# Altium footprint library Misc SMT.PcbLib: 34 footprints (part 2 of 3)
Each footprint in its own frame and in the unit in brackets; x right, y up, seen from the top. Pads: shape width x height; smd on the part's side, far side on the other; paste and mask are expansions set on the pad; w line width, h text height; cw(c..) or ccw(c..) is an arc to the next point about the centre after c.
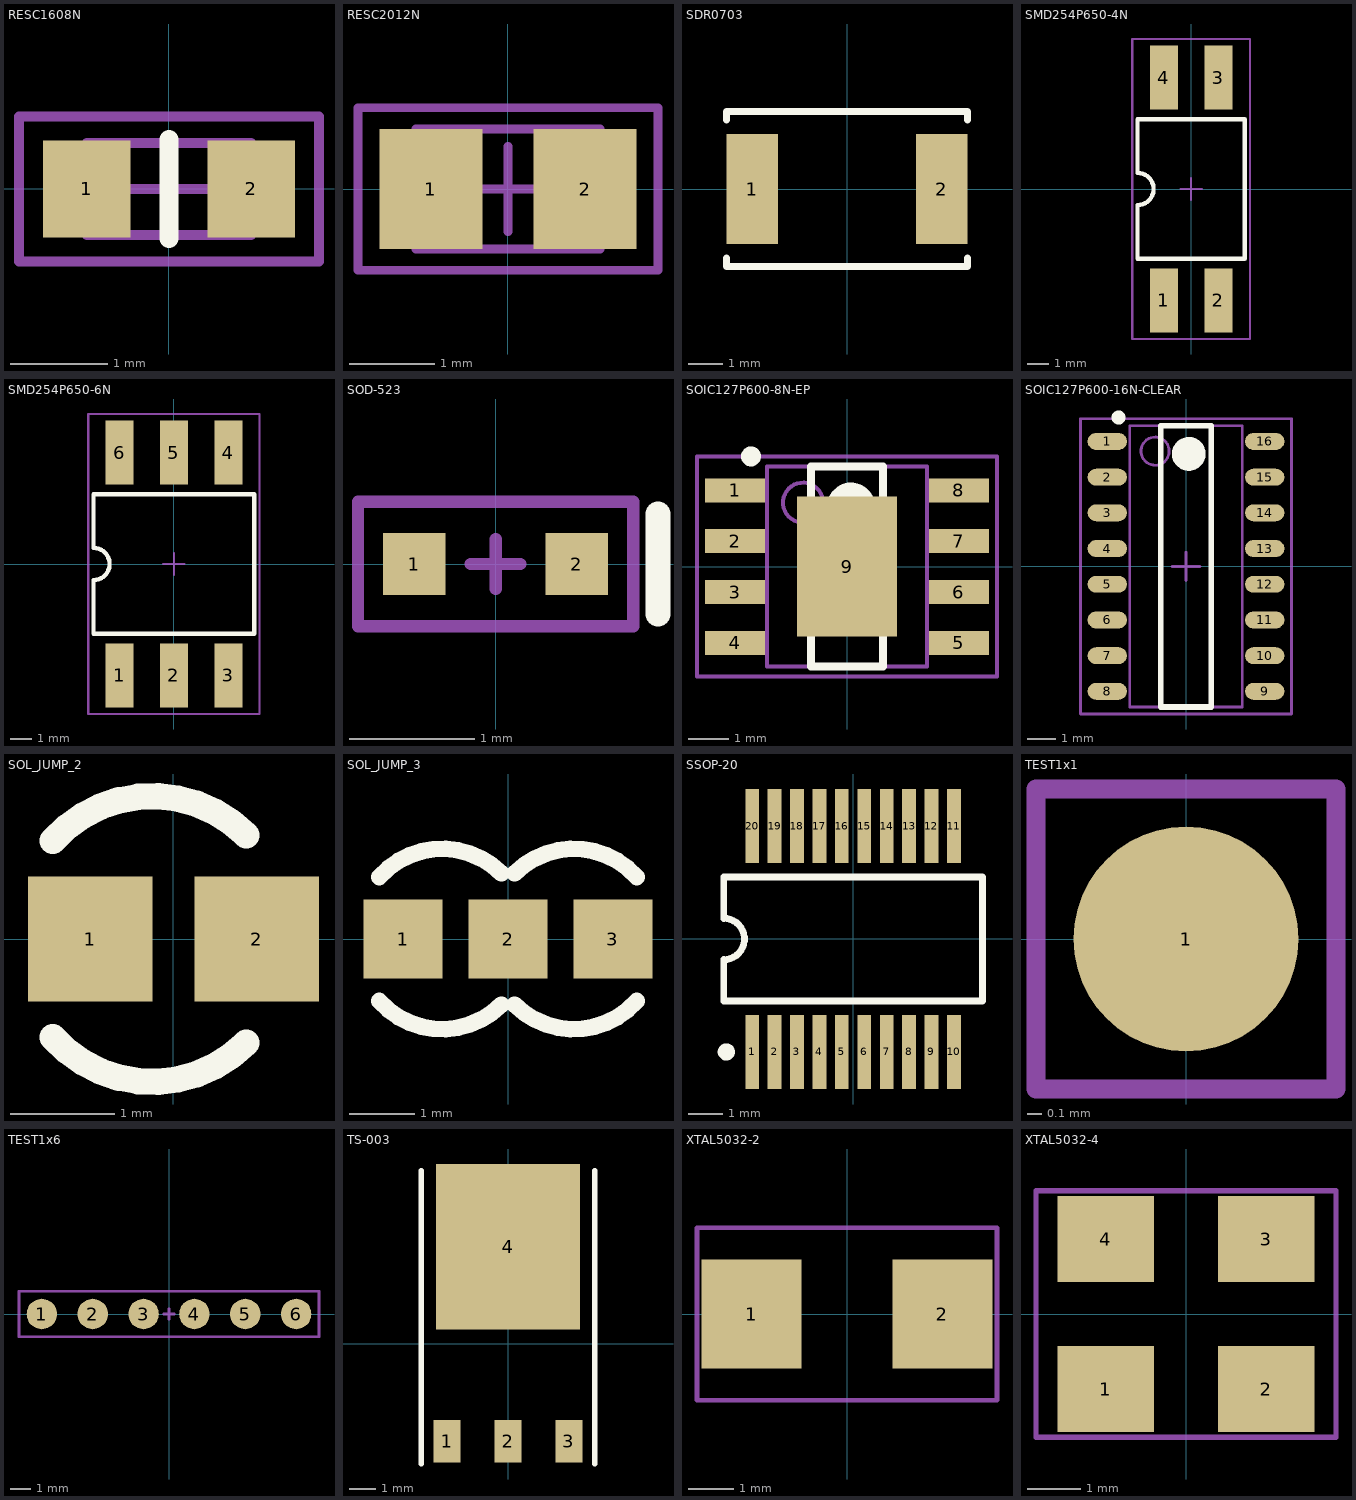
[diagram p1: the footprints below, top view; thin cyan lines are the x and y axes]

## RESC1608N [mm] "Chip Resistor, Body 1.6x0.8mm, IPC Medium Density"
height 0.6
pads (2):
  rect 0.9x1 smd: 1(-0.85,0) 2(0.85,0)
Top Overlay:
  lines w0.2: 0,-0.508 0,0.508
Mechanical 13:
  lines w0.1: -0.85,-0.475 0.85,-0.475 0.85,0.475 -0.85,0.475 -0.85,-0.475
Mechanical 15:
  lines w0.1: -0.475,0 0.475,0 ; 0,-0.475 0,0.475 ; -1.55,-0.75 1.55,-0.75 1.55,0.75 -1.55,0.75 -1.55,-0.75
3D body: height 0.6, standoff 0, extent -0.85,-0.475 0.85,0.475

## RESC2012N [mm] "Chip Resistor, Body 2.0x1.3mm, IPC Medium Density"
height 0.65
pads (2):
  rect 1.2x1.4 smd: 1(-0.9,0) 2(0.9,0)
Mechanical 13:
  lines w0.1: -1.075,-0.7 -1.075,0.7 1.075,0.7 1.075,-0.7 -1.075,-0.7
Mechanical 15:
  lines w0.1: -0.5,0 0.5,0 ; 0,-0.5 0,0.5 ; -1.75,-0.95 -1.75,0.95 1.75,0.95 1.75,-0.95 -1.75,-0.95
3D body: height 0.65, standoff 0, extent -1.075,-0.7 1.075,0.7

## SDR0703 [mm] "Bourns surface-mount inductor"
height 2.7
pads (2):
  rect 1.5x3.2 smd: 1(-2.75,0) 2(2.75,0)
Top Overlay:
  lines w0.2: -3.5,-2 -3.5,-2.25 3.5,-2.25 3.5,-2 ; -3.5,2 -3.5,2.25 3.5,2.25 3.5,2

## SMD254P650-4N [mm] "SMD, 2.54mm (100mil) pitch, 6.5mm wide body"
height 4
pads (4):
  rect 1.3x3 smd: 1(-1.27,-5.2) 2(1.27,-5.2) 3(1.27,5.2) 4(-1.27,5.2)
Top Overlay:
  lines w0.2: -2.5,-3.25 -2.5,-0.75 ccw(c-2.5,0) -2.5,0.75 -2.5,3.25 2.5,3.25 2.5,-3.25 -2.5,-3.25
Mechanical 15:
  lines w0.1: -0.5,0 0.5,0 ; 0,-0.5 0,0.5 ; -2.75,-7 -2.75,7 2.75,7 2.75,-7 -2.75,-7
3D body: height 3.5, standoff 0, extent -2.5,-3.25 2.5,3.25

## SMD254P650-6N [mm] "SMD, 2.54mm (100mil) pitch, 6.5mm wide body"
height 3.5
pads (6):
  rect 1.3x3 smd: 1(-2.54,-5.2) 2(0,-5.2) 3(2.54,-5.2) 4(2.54,5.2) 5(0,5.2) 6(-2.54,5.2)
Top Overlay:
  lines w0.2: -3.75,-3.25 -3.75,-0.75 ccw(c-3.75,0) -3.75,0.75 -3.75,3.25 3.75,3.25 3.75,-3.25 -3.75,-3.25
Mechanical 15:
  lines w0.1: -0.5,0 0.5,0 ; 0,-0.5 0,0.5 ; -4,-7 -4,7 4,7 4,-7 -4,-7
3D body: height 3.5, standoff 0, extent -3.75,-3.25 3.75,3.25

## SOD-523 [mm] "Surface-mount diode SOD-523, SC-79"
pads (2):
  rect 0.5x0.5 smd: 1(-0.65,0) 2(0.65,0)
Top Overlay:
  lines w0.2: 1.3,-0.4 1.3,0.4
Mechanical 15:
  lines w0.1: -0.2,0 0.2,0 ; 0,-0.2 0,0.2 ; -1.1,-0.5 -1.1,0.5 1.1,0.5 1.1,-0.5 -1.1,-0.5
3D body: height 0.6, standoff 0, extent -0.6,-0.4 0.6,0.4

## SOIC127P600-8N-EP [mm] "SOIC, 8-Leads, Body 4.9x3.9mm, Pitch 1.27mm, IPC Medium Density"
height 1.75
pads (9):
  rect 1.5x0.6 smd: 1(-2.794,1.905) 2(-2.794,0.635) 3(-2.794,-0.635) 4(-2.794,-1.905) 5(2.794,-1.905) 6(2.794,-0.635) 7(2.794,0.635) 8(2.794,1.905)
  rect 2.5x3.5 smd paste-999: 9(0,0)
Top Overlay:
  circle w0.6: c0.1,1.5 r0.3
  circle w0.25: c-2.4,2.755 r0.125
  lines w0.2: -0.9,-2.5 0.9,-2.5 0.9,2.5 -0.9,2.5 -0.9,-2.5
Top Paste:
  region: -1,1.5 -1,0.25 -0.25,0.25 -0.25,1.5
  region: 1,1.5 1,0.25 0.25,0.25 0.25,1.5
  region: 1,-1.5 1,-0.25 0.25,-0.25 0.25,-1.5
  region: -1,-1.5 -1,-0.25 -0.25,-0.25 -0.25,-1.5
Mechanical 13:
  circle w0.1: c-1.1,1.6 r0.5
  lines w0.1: -2,-2.5 2,-2.5 2,2.5 -2,2.5 -2,-2.5
Mechanical 15:
  lines w0.1: -0.5,0 0.5,0 ; 0,-0.5 0,0.5 ; -3.75,-2.75 3.75,-2.75 3.75,2.75 -3.75,2.75 -3.75,-2.75
3D body: height 1.75, standoff 0, extent -2,-2.5 2,2.5

## SOIC127P600-16N-CLEAR [mm] "SOIC, 16-Leads, Body 9.9x3.9mm, Pitch 1.27mm, IPC Medium Density"
height 1.75
pads (16):
  oval 1.4x0.6 smd: 1(-2.8,4.445) 2(-2.8,3.175) 3(-2.8,1.905) 4(-2.8,0.635) 5(-2.8,-0.635) 6(-2.8,-1.905) 7(-2.8,-3.175) 8(-2.8,-4.445) 9(2.8,-4.445) 10(2.8,-3.175) 11(2.8,-1.905) 12(2.8,-0.635) 13(2.8,0.635) 14(2.8,1.905) 15(2.8,3.175) 16(2.8,4.445)
Top Overlay:
  circle w0.25: c-2.4,5.295 r0.125
  circle w0.6: c0.1,4 r0.3
  lines w0.2: -0.9,-5 -0.9,5 0.9,5 0.9,-5 -0.9,-5
Mechanical 13:
  circle w0.1: c-1.1,4.1 r0.5
  lines w0.1: -2,-5 -2,5 2,5 2,-5 -2,-5
Mechanical 15:
  lines w0.1: -0.5,0 0.5,0 ; 0,-0.5 0,0.5 ; -3.75,-5.25 -3.75,5.25 3.75,5.25 3.75,-5.25 -3.75,-5.25
3D body: height 1.75, standoff 0, extent -2,-5 2,5

## SOL_JUMP_2 [mm] "2 terminal solder jumper"
pads (2):
  rect 1.2x1.2 smd: 1(-0.8,0) 2(0.8,0)
Top Overlay:
  lines w0.254: -1.163,-0.945 ccw(c-0.206,-0.094) 0.7,-1 ; -1.163,0.945 cw(c-0.206,0.094) 0.7,1

## SOL_JUMP_3 [mm] "3 terminal solder jumper"
pads (3):
  rect 1.2x1.2 smd: 1(-1.6,0) 2(0,0) 3(1.6,0)
Top Overlay:
  lines w0.254: -1.963,-0.945 ccw(c-1.006,-0.094) -0.1,-1 ; -1.963,0.945 cw(c-1.006,0.094) -0.1,1 ; 0.1,-1 ccw(c1.006,-0.094) 1.963,-0.945 ; 0.1,1 cw(c1.006,0.094) 1.963,0.945

## SSOP-20 [mm] "SSOP, Plastic; 20 Leads; Body Width 5.3 mm; Pitch 0.65 mm"
height 1.99
pads (20):
  rect 0.4x2.15 smd: 1(-2.925,-3.275) 2(-2.275,-3.275) 3(-1.625,-3.275) 4(-0.975,-3.275) 5(-0.325,-3.275) 6(0.325,-3.275) 7(0.975,-3.275) 8(1.625,-3.275) 9(2.275,-3.275) 10(2.925,-3.275) 11(2.925,3.275) 12(2.275,3.275) 13(1.625,3.275) 14(0.975,3.275) 15(0.325,3.275) 16(-0.325,3.275) 17(-0.975,3.275) 18(-1.625,3.275) 19(-2.275,3.275) 20(-2.925,3.275)
Top Overlay:
  circle w0.25: c-3.675,-3.275 r0.125
  lines w0.2: -3.75,-1.8 3.75,-1.8 3.75,1.8 -3.75,1.8 -3.75,0.6 cw(c-3.75,0) -3.75,-0.6 -3.75,-1.8
3D body: height 2, standoff 0.05, extent -3.6,-2.7 3.7,2.6

## TEST1x1 [mil]
pads (1):
  round 60 smd paste-200: 1(0,0)
Mechanical 15:
  lines w5: -10,0 10,0 ; 0,-10 0,10 ; -40,-40 40,-40 40,40 -40,40 -40,-40

## TEST1x6 [mil]
pads (6):
  round 60 smd paste-200: 1(-250,0) 2(-150,0) 3(-50,0) 4(50,0) 5(150,0) 6(250,0)
Mechanical 15:
  lines w5: -10,0 10,0 ; 0,-10 0,10 ; -295,-45 295,-45 295,45 -295,45 -295,-45

## TS-003 [mm] "D-PAK/TO-252-AA; 3 Leads (1 Cropped); Body 10.4 (inc. leads) x 6.7 mm (LxW max)"
height 2.38
pads (4):
  rect 1x1.6 smd: 1(-2.285,-3.65) 2(0,-3.65) 3(2.285,-3.65)
  rect 5.4x6.2 smd: 4(0,3.65)
Top Overlay:
  lines w0.2: -3.25,-4.5 -3.25,6.5 ; 3.25,-4.5 3.25,6.5

## XTAL5032-2 [mm] "SMD crystal, 5.0x3.2mm, 2 terminals"
height 1.3
pads (2):
  rect 2.2x2.4 smd paste-0.4: 1(-2.1,0) 2(2.1,0)
Mechanical 15:
  lines w0.1: -3.3,-1.9 3.3,-1.9 3.3,1.9 -3.3,1.9 -3.3,-1.9
3D body: height 1.3, standoff 0, extent -2.5,-1.6 2.5,1.6

## XTAL5032-4 [mm] "SMD crystal, 5.0x3.2mm, 4 terminals"
height 1.3
pads (4):
  rect 1.8x1.6 smd paste-0.3: 1(-1.5,-1.4) 2(1.5,-1.4) 3(1.5,1.4) 4(-1.5,1.4)
Mechanical 15:
  lines w0.1: -2.8,-2.3 -2.8,2.3 2.8,2.3 2.8,-2.3 -2.8,-2.3
3D body: height 0.9, standoff 0, extent -2.5,-1.6 2.5,1.6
